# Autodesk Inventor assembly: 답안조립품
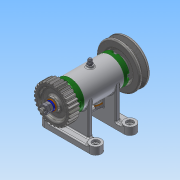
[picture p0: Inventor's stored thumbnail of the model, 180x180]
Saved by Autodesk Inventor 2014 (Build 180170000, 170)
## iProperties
Created: 2015-11
Part Number: 답안조립품
Document SubType Name: Assembly
Designer: 103-23
Author: 103-23
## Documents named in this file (16)
- C:\Users\103-23\Desktop\451110V1022\답안조립품.iam
- C:\Users\103-23\Desktop\451110V1022\1-본체.ipt
- C:\Users\103-23\Desktop\451110V1022\V벨트풀리.ipt
- C:\Users\103-23\Desktop\451110V1022\너트 M 8.ipt
- C:\Users\103-23\Desktop\451110V1022\니플 M 6 x 0.75.ipt
- C:\Users\103-23\Desktop\451110V1022\베어링 15 x 32 x 9.ipt
- C:\Users\103-23\Desktop\451110V1022\볼트 M 6 x 8.ipt
- C:\Users\103-23\Desktop\451110V1022\볼트 M4 x 12.ipt
- C:\Users\103-23\Desktop\451110V1022\스퍼기어.ipt
- C:\Users\103-23\Desktop\451110V1022\스프링와셔 8.ipt
- C:\Users\103-23\Desktop\451110V1022\오일 실 15 25 7.ipt
- C:\Users\103-23\Desktop\451110V1022\와셔 6x11.5.ipt
- C:\Users\103-23\Desktop\451110V1022\와셔 8x17.ipt
- C:\Users\103-23\Desktop\451110V1022\축.ipt
- C:\Users\103-23\Desktop\451110V1022\커버.ipt
- C:\Users\103-23\Desktop\451110V1022\키 3 x 3 x 12.ipt
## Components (12 placed, 4 different names)
1. 1-본체:1
2. V벨트풀리:1 — 각도:2
3. KS B 2023 6002 - 15 x 32 x 9:1
4. KS B 2023 6002 - 15 x 32 x 9:2
5. ISO 4762 M4 x 12:1
6. ISO 4762 M4 x 12:3
7. ISO 4762 M4 x 12:4
8. ISO 4762 M4 x 12:5
9. ISO 4762 M4 x 12:2
10. ISO 4762 M4 x 12:6
11. ISO 4762 M4 x 12:7
12. ISO 4762 M4 x 12:8
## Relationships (1: Angle 1)
- 각도:2 [Angle]: V벨트풀리:1
